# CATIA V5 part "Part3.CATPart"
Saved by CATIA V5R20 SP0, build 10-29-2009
Part number: Part3
Bounding box of the stored display mesh (mm): x 25 to 30, y -4.99 to 144.99, z 60 to 70
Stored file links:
  C:\Users\Ehsan Fathi\Desktop\Part3.CATPart
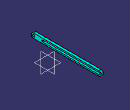
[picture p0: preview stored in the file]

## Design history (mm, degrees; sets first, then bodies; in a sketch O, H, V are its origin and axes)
Body1 (main body)
  DatumSurface1
  DatumCurve1
  Sketch1 on face of DatumSurface1, origin (25, 0, 0), H (0, 1, 0), V (0, 0, 1)
    projected circle E1 centre (0, 65) radius 2.5 from edge of DatumCurve1
    construction line L1 (0, 65) -> (140, 65)
    point P1 (0, 65)
    line L2 (0, 70) -> (140, 70)
    line L3 (140, 60) -> (0, 60)
    arc A1 centre (140, 65) radius 5 from (140, 70) to (140, 60) cw
    arc A2 centre (0, 65) radius 5 from (0, 60) to (0, 70) cw
    construction line L4 (140, 65) -> (20, 65)
    line L5 (140, 63) -> (20, 63)
    line L6 (20, 67) -> (140, 67)
    arc A3 centre (20, 65) radius 2 from (20, 63) to (20, 67) cw
    arc A4 centre (140, 65) radius 2 from (140, 67) to (140, 63) cw
    distance L1 L2 = 5
    length L1 = 140
    distance L4 L5 = 2
    length L4 = 120
    concentricity: P1 E1
    horizontal: L1 H, L4 H
    tangency: A1 L2, A2 L2, A1 L3, A2 L3, A3 L5, A4 L5, A3 L6, A4 L6
  Pad1: profile Sketch1, direction (1, 0, 0), length 5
